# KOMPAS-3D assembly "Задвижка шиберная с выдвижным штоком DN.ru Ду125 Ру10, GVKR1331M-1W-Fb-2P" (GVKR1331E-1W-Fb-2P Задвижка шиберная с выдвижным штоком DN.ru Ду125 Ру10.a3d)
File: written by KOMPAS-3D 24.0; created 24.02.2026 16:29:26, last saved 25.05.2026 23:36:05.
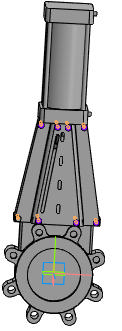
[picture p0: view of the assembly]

Document properties: Автор: R2D2; Полное имя файла: E:\Работа\Зайцев\GVKR1331M-1W-Fb-2P Задвижка шиберная с выдвижным штоком DN.ru Ду50-300 Ру16-10-6 с пневмоприводом\исходные материалы\DN125\GVKR1331E-1W-Fb-2P Задвижка шиберная с выдвижным штоком DN.ru Ду125 Ру10.a3d

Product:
- Component [detail]: Затвор дисковый DN.ru Ду Ру  | qty 1  | pos. 1  | Масса: 18.2; Раздел спецификации: Прочие изделия; Примечание: D050-23732; Автор: R2D2; source file: Задвижка шиберная РЕЗЬБОВОЙ DN.ru Ду Ру.m3d
- Component [detail]: Пневмоцилиндр  | qty 1  | pos. 2  | Масса: 20.781987; Автор: R2D2; source file: Пневмоцилиндр.m3d
- Component [standard]: Hexagon head screw ISO 4017 - М8 x 16  | qty 16  | Масса: 0.012085; Раздел спецификации: Стандартные изделия; Рассекать на разрезах: no
- Component [detail]: лист  | qty 2  | pos. 3  | Масса: 1.314621; Раздел спецификации: Прочие изделия; Примечание: D040-08800; Автор: R2D2; source file: лист.m3d
- Component [detail]: шибер  | qty 1  | pos. 4  | Масса: 1.385554; Раздел спецификации: Прочие изделия; Примечание: D040-08800; Автор: R2D2; source file: шибер.m3d
- Part/product: Задвижка шиберная с выдвижным штоком DN.ru Ду125 Ру10  | designation GVKR1331M-1W-Fb-2P
    Масса: 16
    Раздел спецификации: Прочие изделия
    Примечание: D040-08795

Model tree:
1. Точка:1  (with: Ребро.Отверстие в листовом теле:2)
     X = -44.0115; Y = 127.5; Z = 46
2. Точка:2  (with: Ребро.Отверстие в листовом теле:3)
     X = 44.0115; Y = 127.5; Z = 46
3. Точка:3  (with: Ребро.Отверстие в листовом теле:4)
     X = 91.4747; Y = 127.5; Z = 27.5
4. Точка:4  (with: Ребро.Отверстие в листовом теле:5)
     X = -50.233; Y = 349; Z = 27.5
5. Точка:5  (with: Ребро.Отверстие в листовом теле:6)
     X = -12.3041; Y = 349; Z = 46
6. Точка:6  (with: Ребро.Отверстие в листовом теле:7)
     X = 12.3041; Y = 349; Z = 46
7. Точка:7  (with: Ребро.Отверстие в листовом теле:8)
     X = 50.233; Y = 349; Z = 27.5
8. Массив по точкам:1
9. Экземпляр ( 6 )
10. Экземпляр ( 4 )
11. Экземпляр ( 1 )
12. Экземпляр ( 7 )
13. Экземпляр ( 3 )
14. Экземпляр ( 5 )
15. Экземпляр ( 2 )
16. Контекстная связь:1  (with: Эскиз:7, Грань.Элемент выдавливания:6, Ребро.Элемент выдавливания:6, Ребро.Элемент выдавливания:12, Контекстная связь (лист (1)):1)
17. Контекстная связь:2  (with: Эскиз:6, Грань.Элемент выдавливания:15, Ребро.Элемент выдавливания:15, Контекстная связь (лист (1)):2)
18. Контекстная связь:3  (with: Эскиз:5, Грань.Элемент выдавливания:1, Вершина.Элемент выдавливания:15, Контекстная связь (шибер):3, Грань.Элемент выдавливания:8, Грань.Отверстие в листовом теле:1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)
     Ориентация = 2; Ориентация = 2; Ориентация = 2; Ориентация = 2; Ориентация = 2; Ориентация = 2; Ориентация = 2; Ориентация = 2; Ориентация = 2

Expressions: D050-23732; D040-08800
Referenced files in E:\Работа\Зайцев\GVKR1331M-1W-Fb-2P Задвижка шиберная с выдвижным штоком DN.ru Ду50-300 Ру16-10-6 с пневмоприводом\исходные материалы\DN125\: Задвижка шиберная РЕЗЬБОВОЙ DN.ru Ду Ру.m3d, Пневмоцилиндр.m3d, лист.m3d, шибер.m3d
Referenced files in C:\Program Files\ASCON\KOMPAS-3D v24\Libs\PolynomLib\DATA\vault\Methods\Kompas\3D\: PLib_Bolt_1_ISO_1100.m3d
Referenced files in E:\Работа\Зайцев\GVKR1331E-1W-Fb-2P Задвижка шиберная DN.ru Ду50-300 Ру16-10-6\исходные материалы\DN80\: лист.m3d
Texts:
  Hexagon head screw
  BOSimple***PART:17775d1c-e7de-f283-40f0-d40789f7f59e***SHORTLOC:A259_7B16EF33AB1642D2[13;1,25;16;8;-;Undefined]
  Программные изделия  и базы данных
  GVKR1331M-1W-Fb-2P
  Hexagon head screw ISO 4017 - М8 x 16 (1)
  hole1
  hole2
  лист (1)
  лист (2)
  Hexagon head screw ISO 4017 - М8 x 16 (9)
  Hexagon head screw ISO 4017 - М8 x 16 (10)
  Hexagon head screw ISO 4017 - М8 x 16 (11)
  Hexagon head screw ISO 4017 - М8 x 16 (12)
  Hexagon head screw ISO 4017 - М8 x 16 (13)
  Hexagon head screw ISO 4017 - М8 x 16 (14)
  Hexagon head screw ISO 4017 - М8 x 16 (15)
  Hexagon head screw ISO 4017 - М8 x 16 (16)
  Ось Y.Начало координат
  Плоскость ZY.Начало координат
  Плоскость ZX.Начало координат
  Плоскость XY.Начало координат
